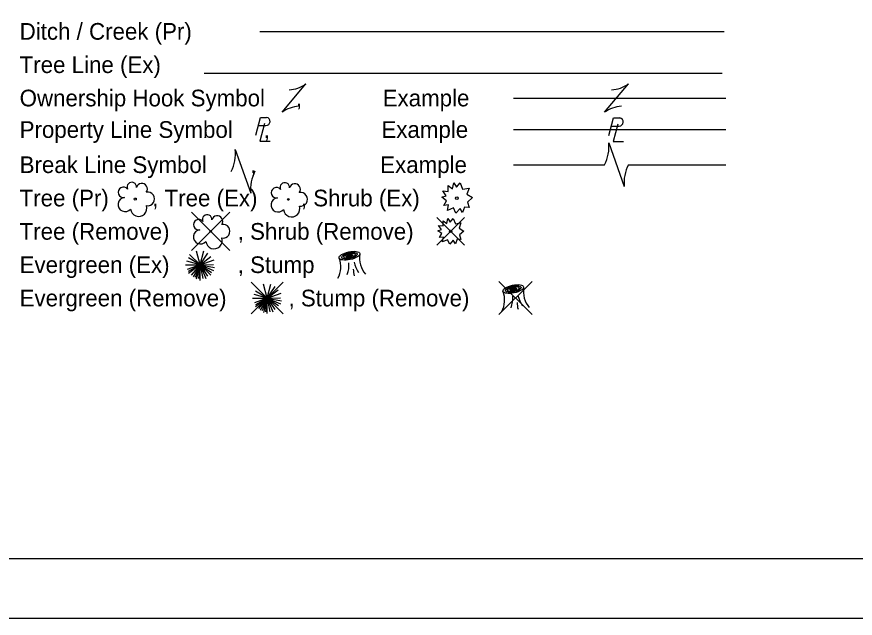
# Model space of a CAD drawing. Extents: x -13.9 to 69.1, y -25.2 to 26.1.
# Drawn here: x 7.96 to 15, y 0 to 5.05 of the extents above; entities that cross this region are included whole.
import ezdxf

# ---------------------------------------------------------------- set-up
doc = ezdxf.new("R2010")
doc.units = 0
for name, color, linetype in [('SH_Border', 7, 'Continuous'), ('SH_Cut_Line', 7, 'Continuous'), ('SH_Text', 7, 'Continuous')]:
    doc.layers.add(name, color=color, linetype=linetype)

msp = doc.modelspace()

# ---------------------------------------------------------------- linework, layer by layer
at = {"layer": 'SH_Border'}
msp.add_lwpolyline([(1.5, 21.5), (33.5, 21.5), (33.5, 0.5), (1.5, 0.5)], close=True, dxfattribs=at)
at = {"layer": 'SH_Cut_Line'}
msp.add_lwpolyline([(0, 0), (34, 0), (34, 22), (0, 22)], close=True, dxfattribs=at)
at = {"layer": 'SH_Text'}
for p, q in [((10.003, 4.9294), (13.903, 4.9294)), ((9.5353, 4.5794), (13.8853, 4.5793)), ((10.1903, 4.2494), (10.3903, 4.4894)), ((12.8985, 4.2494), (13.0985, 4.4894)), ((10.2903, 4.3694), (10.2903, 4.3694)), ((12.133, 4.3694), (13.9153, 4.3694)), ((12.9985, 4.3694), (12.9985, 4.3694)), ((9.9906, 4.1384), (10.0554, 4.1384)), ((10.0307, 4.1072), (10.0307, 4.1072)), ((12.133, 4.1047), (13.9153, 4.1047)), ((12.9562, 4.1343), (13.021, 4.1343)), ((12.9963, 4.1031), (12.9963, 4.1031)), ((12.9335, 3.9935), (13.0635, 3.6253)), ((9.7979, 3.9379), (9.9278, 3.5697)), ((12.133, 3.8094), (12.8986, 3.8094)), ((12.9985, 3.8094), (12.9985, 3.8094)), ((13.0984, 3.8094), (13.9153, 3.8094)), ((9.8629, 3.7538), (9.8629, 3.7538)), ((9.4307, 3.4097), (9.7515, 3.0889)), ((9.7515, 3.4097), (9.4307, 3.0889)), ((11.4898, 3.3652), (11.7216, 3.1335)), ((11.7216, 3.3652), (11.4898, 3.1335)), ((9.5911, 3.2493), (9.5911, 3.2493)), ((11.6057, 3.2494), (11.6057, 3.2494)), ((9.5016, 2.9691), (9.4143, 3.0563)), ((9.5016, 2.9691), (9.4707, 3.0845)), ((9.5016, 2.9691), (9.533, 3.0866)), ((9.5016, 2.9691), (9.5679, 3.0663)), ((9.5016, 2.9691), (9.593, 3.0393)), ((9.3782, 2.9691), (9.5016, 2.9691)), ((9.5016, 2.9691), (9.3912, 2.9987)), ((9.5016, 2.9691), (9.3943, 2.9301)), ((9.5016, 2.9691), (9.402, 2.9121)), ((9.5016, 2.9691), (9.4039, 3.0265)), ((9.5016, 2.9691), (9.4039, 2.8943)), ((9.5016, 2.9691), (9.4279, 2.8825)), ((9.5016, 2.9691), (9.4436, 2.8688)), ((9.5016, 2.9691), (9.4599, 2.8606)), ((9.5016, 2.9691), (9.47, 2.8477)), ((9.5016, 2.9691), (9.488, 2.8543)), ((9.5016, 2.9691), (9.62, 3.0093)), ((9.5016, 2.9691), (9.6143, 2.9714)), ((9.5016, 2.8381), (9.5016, 2.9691)), ((9.5016, 2.9691), (9.5246, 2.8532)), ((9.5016, 2.9691), (9.5499, 2.8524)), ((9.5016, 2.9691), (9.565, 2.8743)), ((9.5016, 2.9691), (9.5913, 2.8811)), ((9.5016, 2.9691), (9.5971, 2.9053)), ((9.5016, 2.9691), (9.6132, 2.9206)), ((9.5016, 2.9691), (9.6223, 2.9452)), ((10.7752, 2.9694), (10.7752, 2.9694)), ((9.9319, 2.823), (10.1992, 2.5557)), ((10.1992, 2.823), (9.9319, 2.5557)), ((12.0117, 2.8284), (12.2898, 2.5503)), ((12.2898, 2.8284), (12.0117, 2.5503)), ((10.0656, 2.6894), (9.9679, 2.7468)), ((10.0656, 2.6894), (9.9783, 2.7765)), ((10.0656, 2.6894), (10.0347, 2.8047)), ((10.0656, 2.6894), (10.097, 2.8068)), ((10.0656, 2.6894), (10.1319, 2.7865)), ((10.0656, 2.6894), (10.157, 2.7595)), ((9.9422, 2.6894), (10.0656, 2.6894)), ((10.0656, 2.6894), (9.9552, 2.7189)), ((10.0656, 2.6894), (9.9583, 2.6503)), ((10.0656, 2.6894), (9.966, 2.6323)), ((10.0656, 2.6894), (9.9679, 2.6145)), ((10.0656, 2.6894), (9.9919, 2.6027)), ((10.0656, 2.6894), (10.0076, 2.589)), ((10.0656, 2.6894), (10.0239, 2.5809)), ((10.0656, 2.6894), (10.034, 2.5679)), ((10.0656, 2.6894), (10.052, 2.5746)), ((10.0656, 2.6894), (10.184, 2.7295)), ((10.0656, 2.6894), (10.1783, 2.6916)), ((10.0656, 2.5584), (10.0656, 2.6894)), ((10.0656, 2.6894), (10.0886, 2.5734)), ((10.0656, 2.6894), (10.1139, 2.5726)), ((10.0656, 2.6894), (10.129, 2.5945)), ((10.0656, 2.6894), (10.1553, 2.6013)), ((10.0656, 2.6894), (10.1611, 2.6255)), ((10.0656, 2.6894), (10.1772, 2.6408)), ((10.0656, 2.6894), (10.1863, 2.6654)), ((10.0656, 2.6894), (10.0656, 2.6894)), ((12.1508, 2.6894), (12.1508, 2.6894)), ((12.1508, 2.6894), (12.1508, 2.6894))]:
    msp.add_line(p, q, dxfattribs=at)
for points in [[(9.9696, 4.0588), (10.0087, 4.207), (10.0603, 4.2069)], [(10.044, 4.1552), (10.0044, 4.0074), (10.0917, 4.0074)], [(12.9352, 4.0547), (12.9743, 4.2029), (13.026, 4.2028)], [(13.0096, 4.1511), (12.97, 4.0033), (13.0574, 4.0033)], [(11.6544, 3.6199), (11.6847, 3.6566), (11.7054, 3.6039), (11.76, 3.6129), (11.7431, 3.5624), (11.7903, 3.5326), (11.7475, 3.4959), (11.76, 3.4502), (11.7223, 3.4536), (11.7061, 3.4079), (11.6847, 3.4425), (11.6507, 3.4017), (11.6293, 3.446), (11.5783, 3.4245), (11.5879, 3.4716), (11.5473, 3.4674), (11.571, 3.5069), (11.5326, 3.5354), (11.5695, 3.5485), (11.5392, 3.5887), (11.5857, 3.5832), (11.5842, 3.6351), (11.6219, 3.6067), (11.6322, 3.6559), (11.6544, 3.6199)], [(11.6021, 3.3263), (11.6278, 3.3575), (11.6454, 3.3127), (11.6918, 3.3204), (11.6774, 3.2774), (11.7176, 3.2521), (11.6812, 3.2209), (11.6918, 3.1821), (11.6598, 3.185), (11.646, 3.1461), (11.6278, 3.1755), (11.599, 3.1408), (11.5807, 3.1785), (11.5374, 3.1602), (11.5455, 3.2003), (11.511, 3.1967), (11.5312, 3.2303), (11.4985, 3.2545), (11.5299, 3.2656), (11.5041, 3.2998), (11.5437, 3.2951), (11.5424, 3.3392), (11.5744, 3.3151), (11.5832, 3.3569), (11.6021, 3.3263)]]:
    msp.add_lwpolyline(points, dxfattribs=at)
for centre, radius in [((8.9581, 3.5212), 0.0084), ((10.2427, 3.5178), 0.0072), ((11.6586, 3.5294), 0.0115), ((9.5911, 3.2493), 0.0072), ((11.6057, 3.2494), 0.00979)]:
    msp.add_circle(centre, radius, dxfattribs=at)
for centre, radius, start, end in [((10.2322, 4.7043), 0.2668, 273.69448, 306.33701), ((12.9404, 4.7043), 0.2668, 273.69448, 306.33701), ((10.3484, 4.0344), 0.2668, 93.69448, 126.33701), ((13.0566, 4.0344), 0.2668, 93.69448, 126.33701), ((10.0551, 4.1728), 0.0345, 270.47098, 81.3281), ((13.0208, 4.1688), 0.0345, 270.47098, 81.3281), ((12.6015, 3.9611), 0.3335, 332.94224, 5.58476), ((9.4659, 3.9054), 0.3335, 332.94224, 5.58476), ((13.3955, 3.6578), 0.3335, 152.94224, 185.58476), ((10.2598, 3.6021), 0.3335, 152.94224, 185.58476), ((8.9285, 3.6223), 0.0395, 354.0047, 205.97412), ((8.8588, 3.5772), 0.0441, 39.06254, 279.54124), ((9.0128, 3.6061), 0.0466, 323.82996, 165.0376), ((10.1434, 3.5737), 0.0441, 39.06254, 279.54124), ((10.2131, 3.6188), 0.0395, 354.0047, 205.97412), ((10.2974, 3.6027), 0.0466, 323.82996, 165.0376), ((8.8724, 3.4748), 0.0592, 96.17219, 320.57371), ((9.0619, 3.5223), 0.0574, 259.14531, 101.45961), ((10.157, 3.4713), 0.0592, 96.17219, 320.57371), ((10.3465, 3.5189), 0.0574, 259.14531, 101.45961), ((8.9864, 3.4431), 0.0685, 184.94757, 19.45715), ((10.271, 3.4396), 0.0685, 184.94757, 19.45715), ((9.5615, 3.3503), 0.0395, 354.0047, 205.97412), ((9.6458, 3.3342), 0.0466, 323.82996, 165.0376), ((9.4918, 3.3052), 0.0441, 39.06254, 279.54124), ((9.5055, 3.2029), 0.0592, 96.17219, 320.57371), ((9.6949, 3.2504), 0.0574, 259.14531, 101.45961), ((9.6195, 3.1712), 0.0685, 184.94757, 19.45715), ((11.0555, 3.0264), 0.2146, 171.41061, 219.91939), ((10.4836, 2.952), 0.2001, 331.53375, 20.92689), ((10.4993, 2.9706), 0.2527, 340.79377, 3.54808), ((11.1006, 3.0722), 0.316, 194.9653, 212.12159), ((10.9705, 2.9294), 0.1819, 178.79264, 197.12241), ((12.4311, 2.7464), 0.2146, 171.41061, 219.91939), ((11.8592, 2.672), 0.2001, 331.53375, 20.92689), ((11.8749, 2.6906), 0.2527, 340.79377, 3.54808), ((12.4762, 2.7922), 0.316, 194.9653, 212.12159), ((12.346, 2.6494), 0.1819, 178.79264, 197.12241)]:
    msp.add_arc(centre, radius, start, end, dxfattribs=at)
for centre, major_axis in [((10.7565, 3.0449), (0.0868, 0.0187)), ((10.7565, 3.0449), (0.0651, 0.0141)), ((10.7565, 3.0449), (0.0488, 0.0105)), ((10.7565, 3.0449), (0.0275, 0.0059)), ((10.7565, 3.0449), (0.0154, 0.0033)), ((12.132, 2.7649), (0.0868, 0.0187)), ((12.132, 2.7649), (0.0651, 0.0141)), ((12.132, 2.7649), (0.0488, 0.0105)), ((12.132, 2.7649), (0.0275, 0.0059)), ((12.132, 2.7649), (0.0154, 0.0033))]:
    msp.add_ellipse(centre, major_axis=major_axis, ratio=0.36865, dxfattribs=at)

# ---------------------------------------------------------------- texts
for s, p in [('Ditch / Creek (Pr)', (7.9867, 4.8594)), ('Tree Line (Ex)', (7.9867, 4.5794)), ('Ownership Hook Symbol     ,             Example', (7.9867, 4.2994)), ('Property Line Symbol     ,                  Example', (7.9867, 4.0347)), ('Break Line Symbol       ,                    Example', (7.9867, 3.7394)), ('Tree (Pr)       , Tree (Ex)       , Shrub (Ex)', (7.9867, 3.4594)), ('Tree (Remove)           , Shrub (Remove)', (7.9867, 3.1794)), ('Evergreen (Ex)           , Stump ', (7.9867, 2.8994)), ('Evergreen (Remove)          , Stump (Remove)', (7.9867, 2.6194))]:
    msp.add_text(s, height=0.14, dxfattribs=at).set_placement(p)

doc.saveas('drawing.dxf')
